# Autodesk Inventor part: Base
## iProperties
Created: 2007-11
Part Number: Base
Material: Steel, Mild
Document SubType Name: Modeling
Designer: CM
Mass: 13708.9 g
Surface Area: 3149.54 cm^2
Volume: 1744.13 cm^3
Density: 7.86 g/cm^3
Author: CM
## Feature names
1. Extrusion1
2. Fillet1
3. Hole1
